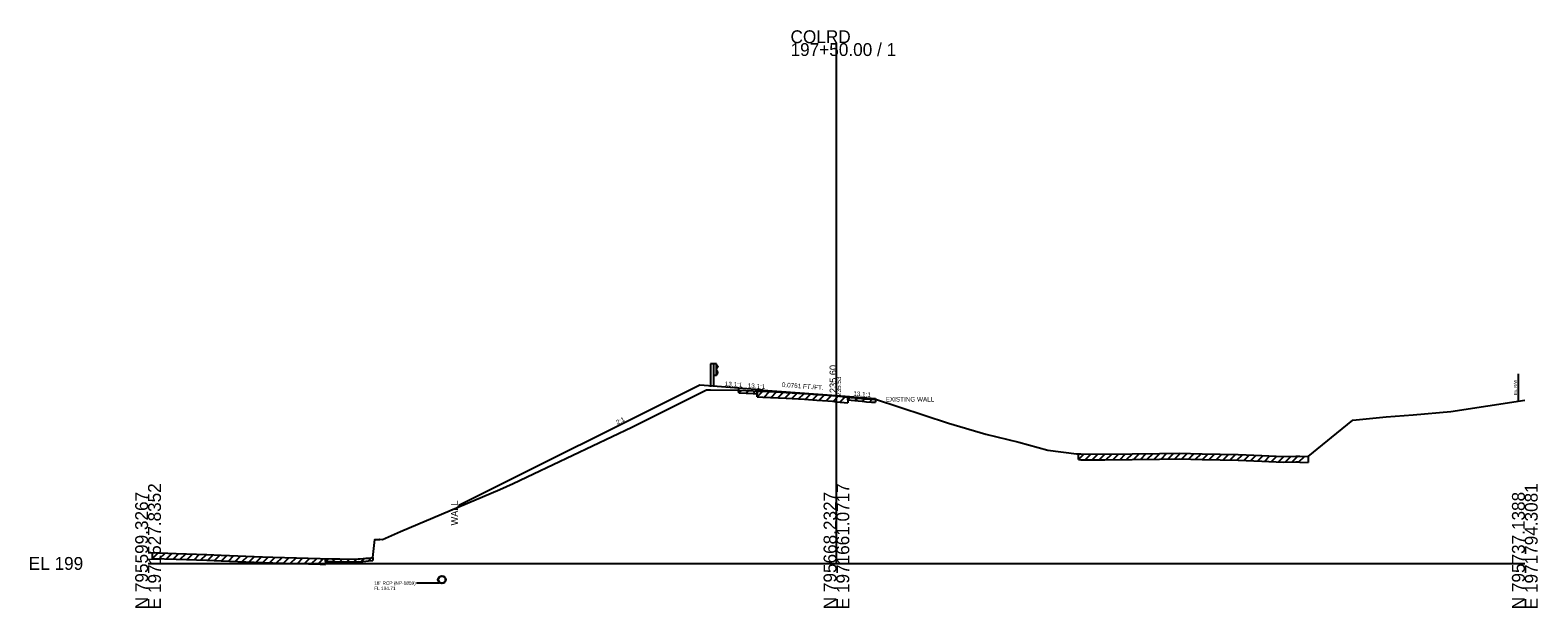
# Model space of a CAD drawing. Extents: x -26 to 1971520, y -10 to 796285.
# Drawn here: x -25.7 to 302.8, y 2490.3 to 2616.3 of the extents above; entities that cross this region are included whole.
import ezdxf

# ---------------------------------------------------------------- set-up
doc = ezdxf.new("R2010")
doc.units = 0
for name, color, linetype in [('RD_GPK_XS_Cell', 7, 'Continuous'), ('RD_XS_Base', 7, 'Continuous'), ('RD_XS_Box', 7, 'Continuous'), ('RD_XS_EarthShd', 7, 'Continuous'), ('RD_XS_ExGround', 7, 'Continuous'), ('RD_XS_ExPaveRet', 7, 'Continuous'), ('RD_XS_ExRW', 7, 'Continuous'), ('RD_XS_GR', 7, 'Continuous'), ('RD_XS_Misc_Line', 7, 'Continuous'), ('RD_XS_Pave', 7, 'Continuous'), ('RD_XS_PaveOvlay', 7, 'Continuous'), ('RD_XS_PaveShd', 7, 'Continuous'), ('RD_XS_Pipe', 7, 'Continuous'), ('RD_XS_TieSlope', 7, 'Continuous'), ('RD_XS_TX_Elev_EX', 7, 'Continuous'), ('RD_XS_TX_Elev_PR', 7, 'Continuous'), ('RD_XS_TX_Notes', 7, 'Continuous'), ('RD_XS_TX_Profile', 7, 'Continuous'), ('RD_XS_TX_ShdSlope', 7, 'Continuous'), ('RD_XS_TX_Slope', 7, 'Continuous')]:
    doc.layers.add(name, color=color, linetype=linetype)

msp = doc.modelspace()

# ---------------------------------------------------------------- linework, layer by layer
at = {"layer": 'RD_GPK_XS_Cell'}
for p, q in [((150, 2500), (150, 2613.48)), ((0, 2500), (150, 2500)), ((150, 2500), (300, 2500))]:
    msp.add_line(p, q, dxfattribs=at)
at = {"layer": 'RD_XS_Base'}
msp.add_line((128.74, 2537.81), (128.74, 2538.22), dxfattribs=at)
at = {"layer": 'RD_XS_Box'}
for p, q in [((158.51, 2535.96), (158.51, 2535.81)), ((67.75, 2512.36), (67.75, 2512.61))]:
    msp.add_line(p, q, dxfattribs=at)
at = {"layer": 'RD_XS_EarthShd'}
msp.add_line((128.74, 2538.22), (120.26, 2538.87), dxfattribs=at)
at = {"layer": 'RD_XS_ExGround'}
msp.add_lwpolyline([(0, 2502.38), (0.64, 2502.36), (6.12, 2502.17), (12.8, 2501.95), (15.91, 2501.83), (24.94, 2501.46), (27.21, 2501.39), (37.49, 2501.07), (40.06, 2501.02), (41.76, 2500.98), (42.55, 2500.96), (45.79, 2501.04), (46.21, 2501), (47.42, 2501.12), (48.01, 2501.17), (49.01, 2501.29), (49.39, 2505.19), (50.49, 2505.2), (50.5, 2505.31), (51.08, 2505.2), (55.02, 2506.93), (76.63, 2516.16), (79.53, 2517.42), (84, 2519.53), (105.44, 2529.72), (119.67, 2536.87), (121.65, 2537.83), (122.57, 2537.83), (128.37, 2537.82), (128.74, 2537.81), (131.84, 2537.67), (132.84, 2537.61), (133.99, 2537.55), (139.06, 2537.29), (143.04, 2537.06), (145.75, 2536.87), (148.14, 2536.68), (149.15, 2536.61), (150, 2536.53), (154.74, 2536.07), (155.59, 2535.98), (156.57, 2535.87), (157.63, 2535.8), (158.51, 2535.83), (174.4, 2530.63), (182.57, 2528.22), (189.76, 2526.44), (196.06, 2524.73), (202.31, 2523.94), (202.72, 2523.89), (203.24, 2523.88), (208.48, 2523.83), (220.38, 2524), (224.65, 2524.04), (229.72, 2523.93), (237.56, 2523.76), (242.69, 2523.53), (247.35, 2523.31), (250.11, 2523.38), (250.62, 2523.38), (251, 2523.37), (252.78, 2523.29), (259.04, 2528.39), (262.56, 2531.27), (269.82, 2532), (275.69, 2532.44), (283.9, 2533.17), (300, 2535.61)], dxfattribs=at)
at = {"layer": 'RD_XS_ExPaveRet'}
for p, q in [((128.74, 2537.19), (128.74, 2537.81)), ((128.74, 2537.19), (131.84, 2537.04)), ((131.84, 2537.04), (132.75, 2536.99)), ((132.75, 2536.36), (132.75, 2537.61)), ((132.75, 2537.61), (132.75, 2536.99)), ((132.75, 2536.36), (132.84, 2536.36)), ((132.84, 2536.36), (133.99, 2536.3)), ((133.99, 2536.3), (139.06, 2536.04)), ((152.51, 2536.28), (152.51, 2535.03)), ((152.51, 2535.66), (152.51, 2536.28)), ((139.06, 2536.04), (143.04, 2535.81)), ((143.04, 2535.81), (145.75, 2535.62)), ((145.75, 2535.62), (148.14, 2535.43)), ((148.14, 2535.43), (149.15, 2535.36)), ((149.15, 2535.36), (150, 2535.28)), ((150, 2535.28), (152.51, 2535.03)), ((152.51, 2535.66), (154.74, 2535.44)), ((154.74, 2535.44), (155.59, 2535.36)), ((155.59, 2535.36), (156.57, 2535.24)), ((156.57, 2535.24), (157.63, 2535.17)), ((157.63, 2535.17), (158.51, 2535.21)), ((158.51, 2535.83), (158.51, 2535.21)), ((202.72, 2522.64), (202.72, 2523.89)), ((252.78, 2523.29), (252.78, 2522.04)), ((202.72, 2522.64), (203.24, 2522.63)), ((203.24, 2522.63), (208.48, 2522.58)), ((208.48, 2522.58), (220.38, 2522.75)), ((220.38, 2522.75), (224.65, 2522.79)), ((224.65, 2522.79), (229.72, 2522.68)), ((229.72, 2522.68), (237.56, 2522.51)), ((237.56, 2522.51), (242.69, 2522.28)), ((242.69, 2522.28), (247.35, 2522.06)), ((247.35, 2522.06), (250.11, 2522.13)), ((250.11, 2522.13), (250.62, 2522.13)), ((250.62, 2522.13), (251, 2522.12)), ((251, 2522.12), (252.78, 2522.04)), ((1, 2501.1), (1, 2502.35)), ((1, 2501.1), (6.12, 2500.92)), ((6.12, 2500.92), (12.8, 2500.7)), ((12.8, 2500.7), (15.91, 2500.58)), ((15.91, 2500.58), (24.94, 2500.21)), ((24.94, 2500.21), (27.21, 2500.14)), ((27.21, 2500.14), (37.49, 2499.82)), ((38.65, 2501.05), (38.65, 2499.8)), ((38.65, 2500.42), (38.65, 2501.05)), ((38.65, 2500.42), (40.06, 2500.39)), ((40.06, 2500.39), (41.76, 2500.36)), ((41.76, 2500.36), (42.55, 2500.34)), ((42.55, 2500.34), (45.79, 2500.42)), ((45.79, 2500.42), (46.21, 2500.37)), ((46.21, 2500.37), (47.42, 2500.49)), ((47.42, 2500.49), (48.01, 2500.55)), ((48.01, 2500.55), (49.01, 2500.66)), ((49.01, 2501.29), (49.01, 2500.66)), ((37.49, 2499.82), (38.65, 2499.8))]:
    msp.add_line(p, q, dxfattribs=at)
at = {"layer": 'RD_XS_ExRW'}
msp.add_line((298.52, 2541.39), (298.52, 2535.39), dxfattribs=at)
at = {"layer": 'RD_XS_GR'}
for p, q in [((123.2, 2543.56), (122.53, 2543.56)), ((122.53, 2543.56), (122.53, 2538.51)), ((123.86, 2543.56), (123.2, 2543.56)), ((123.2, 2543.56), (123.2, 2538.62)), ((123.86, 2540.99), (123.86, 2543.56)), ((123.86, 2543.4), (124.14, 2542.96)), ((124.14, 2542.85), (123.86, 2542.41)), ((124.14, 2542.96), (124.14, 2542.85)), ((123.86, 2540.99), (123.2, 2540.99)), ((124.14, 2541.7), (123.86, 2542.14)), ((123.86, 2541.15), (124.14, 2541.59)), ((124.14, 2541.59), (124.14, 2541.7))]:
    msp.add_line(p, q, dxfattribs=at)
at = {"layer": 'RD_XS_Misc_Line'}
for p, q in [((128.74, 2537.19), (129.36, 2537.79)), ((130.3, 2537.12), (130.92, 2537.71)), ((131.86, 2537.04), (132.47, 2537.63)), ((132.75, 2536.36), (133.93, 2537.55)), ((134.25, 2536.28), (135.44, 2537.47)), ((135.75, 2536.21), (136.94, 2537.4)), ((137.25, 2536.13), (138.44, 2537.32)), ((138.75, 2536.05), (139.94, 2537.24)), ((140.25, 2535.97), (141.44, 2537.15)), ((141.75, 2535.88), (142.94, 2537.07)), ((143.25, 2535.8), (144.42, 2536.96)), ((144.75, 2535.69), (145.92, 2536.86)), ((146.26, 2535.58), (147.41, 2536.74)), ((147.76, 2535.46), (148.92, 2536.62)), ((149.26, 2535.35), (150.4, 2536.49)), ((150.76, 2535.2), (151.9, 2536.34)), ((152.51, 2535.66), (153.1, 2536.23)), ((154.06, 2535.51), (154.65, 2536.07)), ((155.62, 2535.35), (156.2, 2535.91)), ((157.18, 2535.2), (157.81, 2535.81)), ((202.72, 2522.64), (203.96, 2523.87)), ((204.22, 2522.62), (205.46, 2523.86)), ((205.72, 2522.6), (206.96, 2523.84)), ((207.22, 2522.59), (208.46, 2523.83)), ((208.73, 2522.58), (210, 2523.85)), ((210.23, 2522.6), (211.5, 2523.87)), ((211.73, 2522.63), (213, 2523.89)), ((213.23, 2522.65), (214.5, 2523.92)), ((214.73, 2522.67), (216, 2523.94)), ((216.23, 2522.69), (217.5, 2523.96)), ((217.73, 2522.71), (219, 2523.98)), ((219.23, 2522.73), (220.5, 2524)), ((220.74, 2522.75), (222, 2524.02)), ((222.24, 2522.77), (223.5, 2524.03)), ((223.74, 2522.78), (224.99, 2524.03)), ((225.24, 2522.78), (226.46, 2524)), ((226.74, 2522.75), (227.96, 2523.97)), ((228.24, 2522.71), (229.47, 2523.94)), ((229.74, 2522.68), (230.97, 2523.91)), ((231.24, 2522.65), (232.47, 2523.87)), ((232.74, 2522.62), (233.97, 2523.84)), ((234.25, 2522.58), (235.47, 2523.81)), ((235.75, 2522.55), (236.97, 2523.77)), ((237.25, 2522.52), (238.45, 2523.72)), ((238.75, 2522.46), (239.95, 2523.65)), ((240.25, 2522.39), (241.45, 2523.59)), ((241.75, 2522.33), (242.95, 2523.52)), ((243.25, 2522.26), (244.45, 2523.45)), ((244.75, 2522.18), (245.95, 2523.38)), ((246.25, 2522.11), (247.46, 2523.31)), ((247.76, 2522.07), (249.04, 2523.35)), ((249.26, 2522.11), (250.53, 2523.38)), ((250.76, 2522.13), (251.96, 2523.33)), ((1, 2501.1), (2.21, 2502.31)), ((2.5, 2501.05), (3.71, 2502.26)), ((4, 2501), (5.21, 2502.2)), ((5.5, 2500.95), (6.71, 2502.15)), ((7.01, 2500.9), (8.22, 2502.11)), ((8.51, 2500.85), (9.72, 2502.06)), ((10.01, 2500.8), (11.22, 2502.01)), ((11.51, 2500.75), (12.72, 2501.96)), ((13.01, 2500.7), (14.21, 2501.9)), ((14.51, 2500.64), (15.71, 2501.84)), ((16.01, 2500.58), (17.21, 2501.78)), ((17.51, 2500.51), (18.72, 2501.72)), ((19.01, 2500.45), (20.22, 2501.66)), ((20.52, 2500.39), (21.72, 2501.6)), ((22.02, 2500.33), (23.22, 2501.53)), ((23.52, 2500.27), (24.72, 2501.47)), ((25.02, 2500.21), (26.23, 2501.42)), ((26.52, 2500.17), (27.73, 2501.38)), ((28.02, 2500.12), (29.23, 2501.33)), ((29.52, 2500.07), (30.74, 2501.28)), ((31.02, 2500.03), (32.24, 2501.24)), ((32.53, 2499.98), (33.74, 2501.19)), ((34.03, 2499.93), (35.24, 2501.14)), ((35.53, 2499.89), (36.74, 2501.1)), ((37.03, 2499.84), (38.25, 2501.06)), ((38.65, 2500.42), (39.29, 2501.03)), ((40.21, 2500.39), (40.85, 2501)), ((41.77, 2500.36), (42.4, 2500.97)), ((43.33, 2500.36), (43.99, 2501)), ((44.88, 2500.4), (45.55, 2501.04)), ((46.44, 2500.4), (47.16, 2501.09)), ((48, 2500.54), (48.74, 2501.26))]:
    msp.add_line(p, q, dxfattribs=at)
at = {"layer": 'RD_XS_Pave'}
msp.add_line((134, 2537.82), (150, 2536.6), dxfattribs=at)
at = {"layer": 'RD_XS_PaveOvlay'}
for p, q in [((128.74, 2537.81), (130.29, 2537.74)), ((130.29, 2537.74), (131.84, 2537.67)), ((131.84, 2537.67), (132.75, 2537.61)), ((132.75, 2537.61), (132.84, 2537.61)), ((132.84, 2537.61), (133.99, 2537.55)), ((133.99, 2537.55), (139.06, 2537.29)), ((139.06, 2537.29), (143.04, 2537.06)), ((143.04, 2537.06), (145.75, 2536.87)), ((145.75, 2536.87), (148.14, 2536.68)), ((148.14, 2536.68), (149.15, 2536.61)), ((149.15, 2536.61), (150, 2536.53)), ((150, 2536.53), (152.51, 2536.28)), ((152.51, 2536.28), (154.74, 2536.07)), ((154.74, 2536.07), (156.08, 2535.93)), ((156.08, 2535.93), (156.57, 2535.87)), ((156.57, 2535.87), (157.63, 2535.8)), ((157.63, 2535.8), (158.51, 2535.83))]:
    msp.add_line(p, q, dxfattribs=at)
at = {"layer": 'RD_XS_PaveShd'}
for p, q in [((134, 2537.82), (128.74, 2538.22)), ((150, 2536.6), (158.51, 2535.96))]:
    msp.add_line(p, q, dxfattribs=at)
at = {"layer": 'RD_XS_Pipe'}
msp.add_line((63.52, 2495.71), (58.52, 2495.71), dxfattribs=at)
for radius in [0.85, 0.75]:
    msp.add_circle((64.02, 2496.46), radius, dxfattribs=at)
at = {"layer": 'RD_XS_TieSlope'}
msp.add_line((120.26, 2538.87), (67.75, 2512.61), dxfattribs=at)

# ---------------------------------------------------------------- texts
at = {"layer": 'RD_GPK_XS_Cell'}
for s, p in [('COLRD', (140, 2613.48)), ('197+50.00 / 1', (140, 2610.68)), ('EL 199', (-26, 2498.6))]:
    msp.add_text(s, height=2.8, dxfattribs=at).set_placement(p)
for s, p in [('E 1971527.8352', (2.8, 2490)), ('E 1971661.0717', (152.8, 2490)), ('E 1971794.3081', (302.8, 2490)), ('N 795599.3267', (0, 2490)), ('N 795668.2327', (150, 2490)), ('N 795737.1388', (300, 2490))]:
    msp.add_text(s, height=2.8, rotation=90, dxfattribs=at).set_placement(p)
at = {"layer": 'RD_XS_ExRW'}
msp.add_text('Ex. R/W ', height=0.65, rotation=90, dxfattribs=at).set_placement((298.27, 2536.77))
at = {"layer": 'RD_XS_Pipe'}
for s, p in [('18" RCP (NP-1859)', (49.27, 2495.34)), ('FL 194.71', (49.27, 2494.21))]:
    msp.add_text(s, height=0.75, dxfattribs=at).set_placement(p)
at = {"layer": 'RD_XS_TX_Elev_EX'}
msp.add_text('235.53', height=1, rotation=90, dxfattribs=at).set_placement((151, 2536.53))
at = {"layer": 'RD_XS_TX_Elev_PR'}
msp.add_text(' 235.60', height=1.5, rotation=90, dxfattribs=at).set_placement((150, 2536.6))
at = {"layer": 'RD_XS_TX_Notes'}
msp.add_text('EXISTING WALL', height=1, dxfattribs=at).set_placement((160.73, 2535.31))
msp.add_text('WALL', height=1.5, rotation=90, dxfattribs=at).set_placement((67.54, 2508.29))
at = {"layer": 'RD_XS_TX_Profile'}
msp.add_text('13.1:1', height=1, rotation=355.6474, dxfattribs=at).set_placement((153.64, 2536.58))
at = {"layer": 'RD_XS_TX_ShdSlope'}
msp.add_text('13.1:1', height=1, rotation=355.6474, dxfattribs=at).set_placement((125.64, 2538.71))
at = {"layer": 'RD_XS_TX_Slope'}
for s, rotation, p in [('13.1:1', 355.6474, (130.64, 2538.33)), ('0.0761 FT./FT.', 355.6474, (138.08, 2538.51)), ('2:1', 26.565, (102.27, 2530.25))]:
    msp.add_text(s, height=1, rotation=rotation, dxfattribs=at).set_placement(p)

doc.saveas('drawing.dxf')
